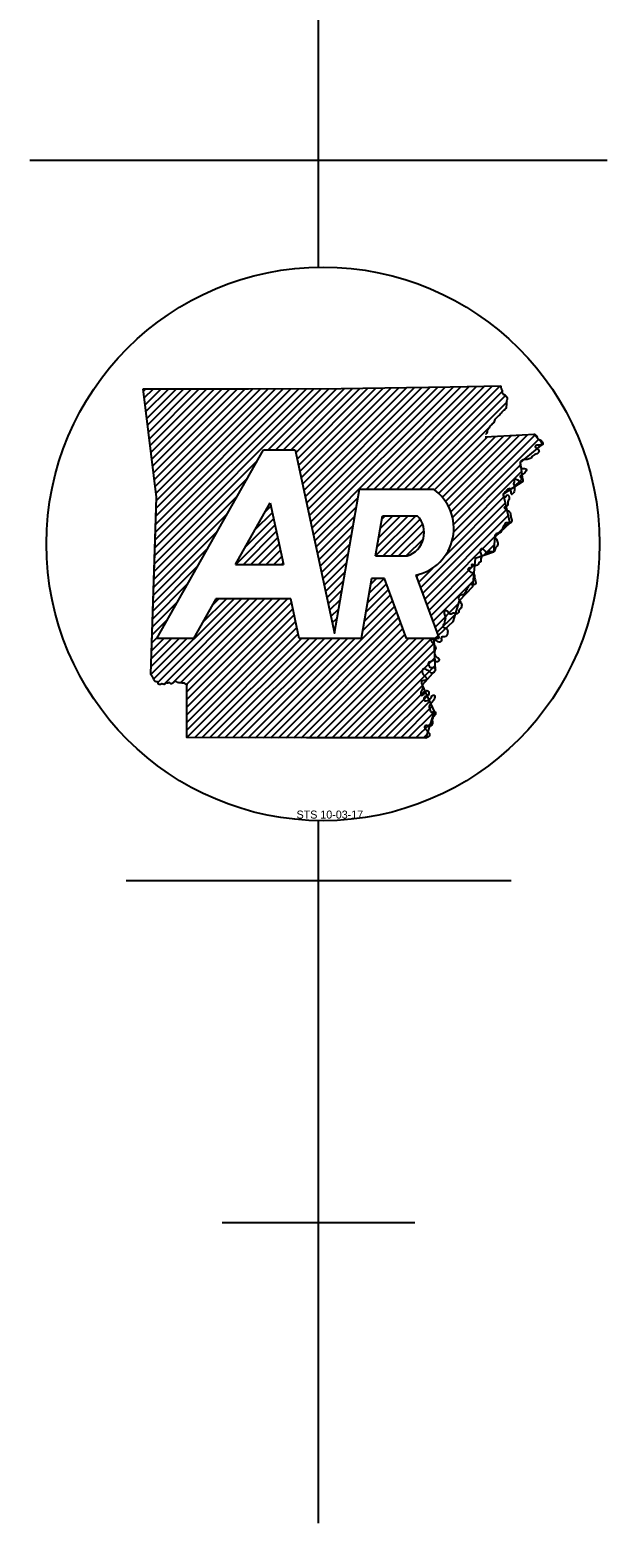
# Model space of a CAD drawing. Extents: x -24122 to 24238, y -8840 to 11381.
# Drawn here: x -5931 to -5405, y 2 to 1361 of the extents above; entities that cross this region are included whole.
import ezdxf

# ---------------------------------------------------------------- set-up
doc = ezdxf.new("R2010")
doc.units = 0
doc.layers.add('R_Annotation', color=7, linetype='Continuous')

msp = doc.modelspace()

# ---------------------------------------------------------------- linework, layer by layer
at = {"layer": 'R_Annotation'}
for p, q in [((-5667.7, 1145.2), (-5667.7, 2721.1)), ((-5930.9, 1242.6), (-5404.6, 1242.6)), ((-5827.3, 1032.3), (-5825.2, 1034.5)), ((-5826.6, 1026.1), (-5818.2, 1034.5)), ((-5825.8, 1019.9), (-5811.2, 1034.5)), ((-5825, 1013.7), (-5804.3, 1034.5)), ((-5824.2, 1007.5), (-5797.3, 1034.5)), ((-5823.5, 1001.3), (-5790.4, 1034.5)), ((-5822.7, 995.1), (-5783.4, 1034.5)), ((-5821.9, 989), (-5776.4, 1034.5)), ((-5821.2, 982.8), (-5769.5, 1034.4)), ((-5820.4, 976.6), (-5762.5, 1034.4)), ((-5819.6, 970.4), (-5755.5, 1034.4)), ((-5818.8, 964.2), (-5748.6, 1034.4)), ((-5818.1, 958), (-5741.6, 1034.4)), ((-5817.3, 951.8), (-5734.7, 1034.4)), ((-5817.1, 882.4), (-5664.9, 1034.6)), ((-5816.8, 889.6), (-5671.8, 1034.6)), ((-5816.6, 896.8), (-5678.8, 1034.5)), ((-5816.5, 945.6), (-5727.7, 1034.4)), ((-5816.4, 904), (-5685.8, 1034.5)), ((-5816.1, 911.2), (-5692.8, 1034.5)), ((-5815.9, 918.4), (-5699.8, 1034.5)), ((-5815.8, 939.4), (-5720.7, 1034.4)), ((-5815.6, 925.6), (-5706.8, 1034.5)), ((-5815.4, 932.8), (-5713.7, 1034.5)), ((-5713.6, 978.8), (-5657.9, 1034.6)), ((-5706.7, 978.8), (-5650.9, 1034.6)), ((-5699.7, 978.8), (-5643.9, 1034.7)), ((-5692.7, 978.8), (-5636.8, 1034.8)), ((-5688.4, 976.2), (-5629.7, 1034.9)), ((-5687.2, 970.5), (-5622.7, 1035)), ((-5685.9, 964.7), (-5615.6, 1035.1)), ((-5684.7, 959), (-5608.5, 1035.2)), ((-5683.5, 953.3), (-5601.4, 1035.3)), ((-5682.3, 947.5), (-5594.4, 1035.4)), ((-5681, 941.8), (-5587.3, 1035.5)), ((-5679.8, 936), (-5580.2, 1035.6)), ((-5678.6, 930.3), (-5573.1, 1035.8)), ((-5677.3, 924.6), (-5566, 1035.9)), ((-5676.1, 918.8), (-5559, 1036)), ((-5674.9, 913.1), (-5551.9, 1036.1)), ((-5673.7, 907.4), (-5544.8, 1036.2)), ((-5672.4, 901.6), (-5537.7, 1036.4)), ((-5624, 943), (-5530.5, 1036.5)), ((-5617.1, 943), (-5523.4, 1036.7)), ((-5610.1, 943), (-5516.3, 1036.9)), ((-5603.1, 943), (-5509.1, 1037)), ((-5596.2, 943), (-5502, 1037.2)), ((-5589.2, 943), (-5500.5, 1031.8)), ((-5582.2, 943), (-5497.1, 1028.2)), ((-5575.3, 943), (-5496.2, 1022.1)), ((-5568.3, 943), (-5512.1, 999.3)), ((-5547.1, 922.5), (-5476.8, 992.8)), ((-5562, 942.4), (-5513.5, 990.9)), ((-5558.2, 939.2), (-5506.1, 991.3)), ((-5554.8, 935.7), (-5498.8, 991.7)), ((-5551.8, 931.7), (-5491.4, 992.1)), ((-5549.2, 927.3), (-5484.1, 992.4)), ((-5545.5, 917.1), (-5470.1, 992.5)), ((-5544.5, 911.1), (-5466.9, 988.7)), ((-5470, 978.7), (-5463.6, 985)), ((-5817.3, 875.2), (-5723.3, 969.2)), ((-5815, 807.2), (-5717.8, 978.8)), ((-5717.8, 978.8), (-5689, 978.8)), ((-5817.6, 868), (-5732.4, 953.1)), ((-5545.9, 895.8), (-5482.7, 959)), ((-5544.5, 904.2), (-5483.5, 965.2)), ((-5490.5, 944.2), (-5481.9, 952.8)), ((-5630.3, 943), (-5562.9, 943)), ((-5817.8, 860.7), (-5741.5, 937)), ((-5743.5, 874.6), (-5711.7, 930.7)), ((-5716.7, 922), (-5711.1, 927.6)), ((-5671.2, 895.9), (-5631.7, 935.4)), ((-5670, 890.1), (-5633.1, 927)), ((-5574.7, 853.1), (-5497.5, 930.3)), ((-5552, 882.7), (-5498.8, 936)), ((-5818, 853.5), (-5750.6, 921)), ((-5734.9, 889.9), (-5708.6, 916.1)), ((-5725.8, 905.9), (-5709.8, 921.9)), ((-5668.7, 884.4), (-5634.6, 918.5)), ((-5615.7, 882.2), (-5579, 918.8)), ((-5614.2, 890.6), (-5586, 918.8)), ((-5612.8, 899), (-5592.9, 918.8)), ((-5611.3, 907.4), (-5599.9, 918.8)), ((-5609.8, 915.9), (-5606.9, 918.8)), ((-5609.3, 918.8), (-5577.6, 918.8)), ((-5608.7, 882.2), (-5575.1, 915.7)), ((-5601.7, 882.2), (-5572.8, 911.1)), ((-5572.8, 848), (-5496.2, 924.6)), ((-5570.9, 842.9), (-5494.9, 919)), ((-5569.1, 837.8), (-5493.6, 913.3)), ((-5818.3, 846.3), (-5759.7, 904.9)), ((-5743.2, 874.6), (-5707.4, 910.4)), ((-5736.2, 874.6), (-5706.2, 904.6)), ((-5729.3, 874.6), (-5704.9, 898.9)), ((-5667.5, 878.7), (-5636.1, 910.1)), ((-5666.3, 872.9), (-5637.6, 901.7)), ((-5594.8, 882.2), (-5571.5, 905.4)), ((-5587.8, 882.2), (-5572.1, 897.9)), ((-5818.5, 839.1), (-5768.8, 888.9)), ((-5722.3, 874.6), (-5703.7, 893.2)), ((-5715.3, 874.6), (-5702.5, 887.4)), ((-5665.1, 867.2), (-5639, 893.2)), ((-5663.8, 861.5), (-5640.5, 884.8)), ((-5517.4, 882.5), (-5507.6, 892.3)), ((-5818.7, 831.9), (-5777.9, 872.8)), ((-5743.5, 874.6), (-5699.7, 874.6)), ((-5708.4, 874.6), (-5701.2, 881.7)), ((-5701.4, 874.6), (-5700, 876)), ((-5662.6, 855.7), (-5642, 876.4)), ((-5615.7, 882.2), (-5586.8, 882.2)), ((-5576.6, 858.2), (-5563.3, 871.4)), ((-5567.2, 832.7), (-5525.4, 874.5)), ((-5819, 824.7), (-5787, 856.7)), ((-5661.4, 850), (-5643.4, 867.9)), ((-5660.2, 844.2), (-5644.9, 859.5)), ((-5623.1, 839.5), (-5605.7, 856.9)), ((-5621.7, 847.9), (-5607.8, 861.8)), ((-5620.2, 856.3), (-5614.7, 861.8)), ((-5607.6, 861.8), (-5619.3, 861.8)), ((-5587.4, 807.2), (-5607.6, 861.8)), ((-5579, 864.7), (-5557.8, 807.2)), ((-5578.4, 863.3), (-5576.3, 865.4)), ((-5565.3, 827.6), (-5526.2, 866.8)), ((-5563.4, 822.6), (-5527, 859)), ((-5818, 770), (-5744.7, 843.2)), ((-5813.8, 767.2), (-5737.8, 843.2)), ((-5808.8, 765.2), (-5730.8, 843.2)), ((-5800.5, 766.6), (-5723.8, 843.2)), ((-5793.5, 766.7), (-5716.9, 843.2)), ((-5788, 765.2), (-5709.9, 843.2)), ((-5787.8, 751.5), (-5696, 843.2)), ((-5787.8, 758.4), (-5702.9, 843.2)), ((-5761.3, 843.2), (-5781.7, 807.2)), ((-5773.8, 821.2), (-5751.7, 843.2)), ((-5764.7, 837.2), (-5758.7, 843.2)), ((-5693, 843.2), (-5761.3, 843.2)), ((-5658.9, 838.5), (-5646.4, 851.1)), ((-5626.1, 822.6), (-5602, 846.7)), ((-5624.6, 831), (-5603.9, 851.8)), ((-5819.2, 817.5), (-5796.1, 840.7)), ((-5787.7, 744.5), (-5692.3, 839.9)), ((-5787.7, 737.6), (-5691.1, 834.2)), ((-5718, 716.7), (-5598.2, 836.5)), ((-5711.1, 716.7), (-5596.3, 831.4)), ((-5657.7, 832.8), (-5647.8, 842.6)), ((-5656.5, 827), (-5649.3, 834.2)), ((-5627.6, 814.1), (-5600.1, 841.6)), ((-5561.5, 817.5), (-5540.2, 838.8)), ((-5819.5, 810.3), (-5805.2, 824.6)), ((-5787.7, 730.6), (-5689.9, 828.5)), ((-5787.7, 723.7), (-5688.6, 822.7)), ((-5787.6, 716.8), (-5687.4, 817)), ((-5704.1, 716.7), (-5594.5, 826.4)), ((-5697.2, 716.7), (-5592.6, 821.3)), ((-5690.2, 716.7), (-5590.7, 816.2)), ((-5655.2, 821.3), (-5650.8, 825.7)), ((-5654, 815.6), (-5652.3, 817.3)), ((-5559.7, 812.4), (-5543.2, 828.9)), ((-5820.5, 774.4), (-5787.7, 807.2)), ((-5820.4, 781.5), (-5794.7, 807.2)), ((-5820.2, 788.7), (-5801.6, 807.2)), ((-5819.9, 795.9), (-5808.6, 807.2)), ((-5819.7, 803.1), (-5814.3, 808.6)), ((-5781.7, 807.2), (-5815, 807.2)), ((-5780.6, 716.8), (-5686.2, 811.3)), ((-5773.7, 716.8), (-5683.2, 807.2)), ((-5766.7, 716.8), (-5676.3, 807.2)), ((-5759.7, 716.8), (-5669.3, 807.2)), ((-5752.8, 716.8), (-5662.3, 807.2)), ((-5745.8, 716.8), (-5655.4, 807.2)), ((-5738.9, 716.8), (-5648.4, 807.2)), ((-5731.9, 716.7), (-5641.4, 807.2)), ((-5725, 716.7), (-5634.5, 807.2)), ((-5628.8, 807.2), (-5685.3, 807.2)), ((-5683.3, 716.7), (-5588.8, 811.1)), ((-5676.3, 716.6), (-5585.7, 807.2)), ((-5669.3, 716.6), (-5578.7, 807.2)), ((-5662.4, 716.6), (-5571.8, 807.2)), ((-5655.4, 716.6), (-5564.8, 807.2)), ((-5648.5, 716.6), (-5562.5, 802.6)), ((-5557.8, 807.2), (-5587.4, 807.2)), ((-5641.5, 716.6), (-5562.2, 795.9)), ((-5634.6, 716.6), (-5561.9, 789.3)), ((-5627.6, 716.6), (-5561.5, 782.6)), ((-5620.7, 716.6), (-5573, 764.2)), ((-5613.7, 716.5), (-5570.8, 759.4)), ((-5606.8, 716.5), (-5568.7, 754.6)), ((-5599.8, 716.5), (-5566.5, 749.8)), ((-5592.8, 716.5), (-5564.4, 745)), ((-5585.9, 716.5), (-5562.6, 739.8)), ((-5578.9, 716.5), (-5565.7, 729.7)), ((-5572, 716.5), (-5568.9, 719.6)), ((-5667.7, 1.5), (-5667.7, 641.1)), ((-5843.1, 586.7), (-5492.2, 586.7)), ((-5755.4, 275.2), (-5580, 275.2))]:
    msp.add_line(p, q, dxfattribs=at)
for points in [[(-5827.6, 1034.4), (-5731.5, 1034.4), (-5647.1, 1034.6), (-5547.7, 1036.1), (-5501.6, 1037.2)], [(-5827.6, 1034.5), (-5731.5, 1034.4), (-5647.2, 1034.6), (-5547.7, 1036.1), (-5501.6, 1037.2)], [(-5820.7, 774.5), (-5815.3, 935.7), (-5827.6, 1034.5)], [(-5817, 885.1), (-5815.3, 935.7), (-5827.6, 1034.4)], [(-5471.4, 993.1), (-5463.1, 984.4), (-5483.8, 967.3), (-5481.6, 950.1), (-5499.3, 938.4), (-5493.2, 912), (-5507, 899.4), (-5508.2, 885.8), (-5524.8, 879.8), (-5527.4, 854.2), (-5539.4, 841.4), (-5545.2, 822.1), (-5562.6, 806.1), (-5561.3, 777.9), (-5573.2, 764.7), (-5562.4, 740.5), (-5569.9, 716.5)], [(-5515.8, 990.8), (-5470.7, 993.1)], [(-5515.8, 990.8), (-5470.7, 993.1)], [(-5689, 978.8), (-5653.2, 811.8), (-5630.3, 943)], [(-5711.7, 930.7), (-5699.7, 874.6)], [(-5615.7, 882.2), (-5609.3, 918.8)], [(-5820.6, 774.5), (-5817, 885.1)], [(-5619.3, 861.8), (-5628.8, 807.2)], [(-5685.3, 807.2), (-5693, 843.2)], [(-5569.9, 716.4), (-5787.7, 716.8), (-5787.8, 764.9)], [(-5569.9, 716.5), (-5787.7, 716.8), (-5787.8, 764.9)]]:
    msp.add_lwpolyline(points, dxfattribs=at)
msp.add_ellipse((-5663.6, 893.2), major_axis=(252.1, 0), ratio=0.999976, dxfattribs=at)
for centre, major_axis, start_param, end_param in [((-5588, 907.4), (-43.6, 0), 1.777838, 4.099264), ((-5593.7, 903.4), (-22.3, 0), 1.887169, 3.90762)]:
    msp.add_ellipse(centre, major_axis=major_axis, ratio=0.999987, start_param=start_param, end_param=end_param, dxfattribs=at)
for points in [[(-5501.6, 1037.2), (-5501.3, 1034.6), (-5500.5, 1033.3), (-5500.4, 1030.7), (-5499.3, 1029.6), (-5497.6, 1028.6), (-5496.1, 1026.9), (-5495.7, 1024.9), (-5496.2, 1022.8), (-5496.3, 1020.4), (-5496.5, 1018.4), (-5496.9, 1016.6), (-5498.3, 1015.1), (-5499.7, 1014.1), (-5500.9, 1012.8), (-5501.8, 1011.5), (-5503.3, 1010.1), (-5504.9, 1008.6), (-5506.2, 1007.3), (-5507.4, 1005.6), (-5508, 1003.8), (-5509.3, 1002.5), (-5510.4, 1001.3), (-5511.9, 999.6), (-5512.6, 998.1), (-5513.9, 996.2), (-5514.2, 994.5), (-5515.1, 993), (-5515.2, 992.8)], [(-5501.6, 1037.2), (-5501.3, 1034.6), (-5500.4, 1033.2), (-5500.3, 1030.7), (-5499.3, 1029.7), (-5497.6, 1028.6), (-5496, 1026.9), (-5495.7, 1024.9), (-5496.2, 1022.8), (-5496.3, 1020.5), (-5496.5, 1018.4), (-5496.9, 1016.6), (-5498.3, 1015.1), (-5499.7, 1014), (-5500.9, 1012.8), (-5501.8, 1011.5), (-5503.3, 1010.1), (-5504.9, 1008.6), (-5506.1, 1007.3), (-5507.4, 1005.6), (-5508, 1003.8), (-5509.4, 1002.5), (-5510.4, 1001.3), (-5511.8, 999.7), (-5512.6, 998.1), (-5513.9, 996.2), (-5514.2, 994.4), (-5515.1, 993), (-5515.2, 992.8)], [(-5471.4, 993.1), (-5470.7, 993.1), (-5468.7, 991), (-5467.8, 989.2), (-5466.5, 988.2), (-5465, 987.7), (-5463.9, 986.3), (-5463.1, 984.8), (-5463.5, 983.5), (-5465.2, 983.4), (-5467.1, 983.1), (-5468.8, 983.1), (-5470.3, 981.9), (-5468.9, 980.3), (-5467.2, 978.8), (-5466.7, 977.2), (-5467.7, 975.7), (-5469.6, 974.9), (-5471.4, 974.1), (-5473.1, 972.7), (-5473.9, 971.4), (-5475.7, 970.8), (-5477.6, 970.2), (-5479.3, 970.1), (-5481.2, 969.7), (-5483, 968.8), (-5483.8, 967.3), (-5483.6, 965.1), (-5483.6, 962.8), (-5481.7, 962), (-5480, 961.9), (-5478.2, 961.1), (-5478.5, 959.7), (-5479.7, 958), (-5481.2, 956.7), (-5482.7, 956.1), (-5484, 954.8), (-5483.6, 953.6), (-5482.3, 952.8), (-5481.4, 951.4), (-5481.6, 950.2), (-5483, 949.3), (-5484.5, 949.6), (-5485.7, 951.1), (-5486.9, 951.6), (-5488.1, 952.1), (-5489.4, 951.4), (-5489.4, 949.6), (-5489.9, 947.8), (-5489.4, 946.4), (-5489, 944.5), (-5489, 943.1), (-5489.4, 941), (-5490.5, 939), (-5491.6, 938.3), (-5492.2, 940.6), (-5492.4, 942.4), (-5493.1, 943.5), (-5494, 943.5), (-5495.3, 942.7), (-5496.6, 941.3), (-5498.3, 939.8), (-5499.4, 938.3), (-5498.8, 936.5), (-5497.5, 936), (-5496.5, 936.4), (-5496, 937.6), (-5495, 937.7), (-5494, 935.9)], [(-5494, 935.9), (-5493.8, 934.2), (-5494.8, 932.3), (-5495.2, 930.5), (-5495, 928.6), (-5496.9, 927.6), (-5498.5, 926.4), (-5497.6, 925), (-5495.8, 923.7), (-5494, 922.7), (-5492.9, 921.7), (-5492.6, 919.3), (-5492.3, 917.7), (-5491.7, 915.6), (-5491.5, 914.1), (-5492.5, 912.3), (-5493.8, 911.9), (-5495.1, 912.3), (-5496.6, 912.5), (-5497.9, 911.3), (-5498.8, 909.6), (-5499.7, 908), (-5500.4, 906.5), (-5501, 905), (-5502.3, 903.2), (-5503.9, 902.9), (-5505.8, 902.4), (-5506.9, 901.1), (-5506.7, 898.9), (-5505.6, 897.5), (-5504.8, 895.6), (-5504.3, 894), (-5504.5, 892), (-5505.4, 890.5), (-5506.4, 889.6), (-5506.9, 887.7), (-5507.7, 886.2), (-5508.4, 885.8), (-5509.8, 885.9), (-5511.4, 886.2), (-5512.7, 886.1), (-5513.9, 885.5), (-5515.2, 885.8), (-5516.5, 887.3), (-5517.6, 888.4), (-5518.8, 888.8), (-5520, 888.1), (-5520.2, 886.1), (-5519.6, 884.1), (-5519.1, 881.4), (-5519.6, 879.7), (-5519.8, 877)], [(-5519.8, 877), (-5521.9, 875.4), (-5522.8, 873.8), (-5528.1, 874.2), (-5528, 872.4), (-5529.9, 871.4), (-5531.5, 870.2), (-5530.6, 868.8), (-5528.8, 867.5), (-5527, 866.5), (-5525.9, 865.5), (-5525.6, 863), (-5525.3, 861.5), (-5524.7, 859.3), (-5524.4, 857.8), (-5525.5, 856.1), (-5526.8, 855.7), (-5528.1, 856.1), (-5529.6, 856.2), (-5530.8, 855.1), (-5531.7, 853.4), (-5532.6, 851.7), (-5533.3, 850.3), (-5534, 848.7), (-5535.2, 846.9), (-5536.8, 846.7), (-5538.8, 846.2), (-5539.9, 844.9), (-5539.7, 842.7), (-5538.6, 841.2), (-5537.8, 839.3), (-5537.2, 837.8), (-5537.5, 835.7), (-5538.3, 834.2), (-5539.4, 833.3), (-5539.9, 831.5), (-5540.7, 830), (-5541.4, 829.6), (-5542.8, 829.7), (-5544.3, 830), (-5545.6, 829.9), (-5546.9, 829.2), (-5548.2, 829.6), (-5549.5, 831), (-5550.5, 832.1), (-5551.7, 832.5), (-5553, 831.9), (-5553.2, 829.9), (-5552.6, 827.9), (-5552.1, 825.1), (-5552.6, 823.5), (-5552.8, 820.7)], [(-5552.8, 820.7), (-5552.9, 820.7), (-5554, 819.3), (-5553.4, 817.2), (-5551.1, 816.4), (-5550, 814.4), (-5550, 812.6), (-5550.7, 810.2), (-5551.8, 809), (-5553.9, 808.5), (-5555.5, 808.2), (-5555.7, 805.5), (-5556.4, 804.1), (-5557.7, 803.7), (-5559.5, 804.6), (-5560.5, 805.1), (-5561.8, 805.7), (-5563.5, 806.6), (-5564.8, 806.4), (-5564.4, 803.8), (-5564.3, 803.7), (-5562.8, 801.8), (-5561.4, 800.2), (-5560.8, 798.4)], [(-5552.8, 820.7), (-5552.9, 820.7), (-5554, 819.3), (-5553.4, 817.2), (-5551.1, 816.4), (-5550, 814.4), (-5550, 812.6), (-5550.7, 810.2), (-5551.8, 809), (-5553.9, 808.5), (-5555.5, 808.2), (-5555.7, 805.5), (-5556.4, 804.1), (-5557.7, 803.7), (-5559.5, 804.6), (-5560.5, 805.1), (-5561.8, 805.7), (-5563.5, 806.6), (-5564.8, 806.4), (-5564.4, 803.8), (-5564.3, 803.7), (-5562.8, 801.8), (-5561.4, 800.2), (-5560.8, 798.4)], [(-5560.8, 798.4), (-5561.3, 797), (-5562, 794.6), (-5561.8, 792.6), (-5560.9, 790.9), (-5559.5, 789.9), (-5557.9, 788.6), (-5558.1, 786.5), (-5559, 785.7), (-5561.1, 786.2), (-5562.7, 787), (-5564, 786.6), (-5565.8, 785.7), (-5567.2, 785.4), (-5567.2, 782.6), (-5565.4, 780.6), (-5563.8, 780.6), (-5561.9, 780.4), (-5561.2, 778.2), (-5562.3, 776.4), (-5564.1, 775.6), (-5566.3, 776.6), (-5567.9, 777.8), (-5569.5, 778.8), (-5571.6, 779.3), (-5572.7, 779.1), (-5573.2, 776.6), (-5572.3, 774.4), (-5570.8, 772.8), (-5569.3, 770.8), (-5569.5, 769.3), (-5570.6, 768.9), (-5572.5, 768.5), (-5573.7, 767.9), (-5573.9, 767.4), (-5573.4, 765.4), (-5572.8, 763.2), (-5572.8, 761.5), (-5573.5, 760), (-5574.5, 757.6), (-5574.4, 756.1), (-5573.7, 755.3), (-5572.8, 755.6), (-5571.6, 756.4), (-5570.8, 757.4), (-5570.1, 758.6), (-5568.9, 759.6), (-5567.4, 758.7), (-5567, 756.8), (-5567.9, 755.2), (-5569.2, 754.5), (-5570.7, 753.9), (-5571.8, 752.6), (-5571.5, 751), (-5570.6, 750.2), (-5568.4, 750.7), (-5567, 751.3), (-5566.1, 752.1), (-5565.1, 753.1), (-5564.6, 754.2), (-5563.8, 755.2), (-5562.4, 755.5), (-5561.8, 754.7), (-5562, 752.6), (-5562.8, 750.7), (-5564, 749.1), (-5565.2, 748), (-5566.8, 745.5), (-5566.5, 743.3), (-5565.8, 741.4), (-5565.1, 740), (-5563.6, 740.3), (-5562, 740.5), (-5561.1, 739.7), (-5561.2, 738), (-5562.4, 736.4), (-5563.5, 734.9), (-5564.1, 732.8), (-5563.8, 731.2), (-5563.8, 729.9), (-5564.3, 728.4), (-5565.1, 727.6), (-5567.4, 727.6), (-5569.7, 727.9), (-5570.9, 727.2), (-5570.7, 725.2), (-5569.3, 723.7), (-5568.4, 722.9), (-5567, 721.2), (-5566.4, 719.9), (-5566.6, 718.7), (-5567.5, 717.6), (-5569.9, 716.4)], [(-5560.8, 798.4), (-5561.3, 797), (-5562, 794.6), (-5561.8, 792.6), (-5560.9, 790.9), (-5559.5, 789.9), (-5557.9, 788.6), (-5558.1, 786.5), (-5559, 785.7), (-5561.1, 786.2), (-5562.7, 787), (-5564, 786.6), (-5565.8, 785.7), (-5567.2, 785.4), (-5567.2, 782.6), (-5565.4, 780.6), (-5563.8, 780.6), (-5561.9, 780.4), (-5561.2, 778.2), (-5562.3, 776.4), (-5564.1, 775.6), (-5566.3, 776.6), (-5567.9, 777.8), (-5569.5, 778.8), (-5571.6, 779.3), (-5572.7, 779.1), (-5573.2, 776.6), (-5572.3, 774.4), (-5570.8, 772.8), (-5569.3, 770.8), (-5569.5, 769.3), (-5570.6, 768.9), (-5572.5, 768.5), (-5573.7, 767.9), (-5573.9, 767.4), (-5573.4, 765.4), (-5572.8, 763.2), (-5572.8, 761.5), (-5573.5, 760), (-5574.5, 757.6), (-5574.4, 756.1), (-5573.7, 755.3), (-5572.8, 755.6), (-5571.6, 756.4), (-5570.8, 757.4), (-5570.1, 758.6), (-5568.9, 759.6), (-5567.4, 758.7), (-5567, 756.8), (-5567.9, 755.2), (-5569.2, 754.5), (-5570.7, 753.9), (-5571.8, 752.6), (-5571.5, 751), (-5570.6, 750.2), (-5568.4, 750.7), (-5567, 751.3), (-5566.1, 752.1), (-5565.1, 753.1), (-5564.6, 754.2), (-5563.8, 755.2), (-5562.4, 755.5), (-5561.8, 754.7), (-5562, 752.6), (-5562.8, 750.7), (-5564, 749.1), (-5565.2, 748), (-5566.8, 745.5), (-5566.5, 743.3), (-5565.8, 741.4), (-5565.1, 740), (-5563.6, 740.3), (-5562, 740.5), (-5561.1, 739.7), (-5561.2, 738), (-5562.4, 736.4), (-5563.5, 734.9), (-5564.1, 732.8), (-5563.8, 731.2), (-5563.8, 729.9), (-5564.3, 728.4), (-5565.1, 727.6), (-5567.4, 727.6), (-5569.7, 727.9), (-5570.9, 727.2), (-5570.7, 725.2), (-5569.3, 723.7), (-5568.4, 722.9), (-5567, 721.2), (-5566.4, 719.9), (-5566.6, 718.7), (-5567.5, 717.6), (-5569.9, 716.4)], [(-5787.8, 764.9), (-5787.5, 764.8), (-5788.7, 765.6), (-5790.2, 766.3), (-5791.9, 766.5), (-5794.1, 766.8), (-5796, 766.9), (-5797.9, 768.2), (-5799.9, 766.9), (-5802.2, 765.9), (-5803.5, 767), (-5805.2, 766.3), (-5806.4, 766.6), (-5808.5, 765.2), (-5810.4, 765.7), (-5811.9, 765.3), (-5813.6, 765.4), (-5814, 767.4), (-5815.7, 767.7), (-5817.2, 768.5), (-5818.2, 770.6), (-5818.9, 772.2), (-5820.7, 774.5)], [(-5787.8, 764.9), (-5787.5, 764.8), (-5788.7, 765.6), (-5790.2, 766.3), (-5792, 766.4), (-5794.2, 766.7), (-5796, 766.9), (-5797.9, 768.2), (-5799.9, 766.9), (-5802.2, 765.9), (-5803.5, 767), (-5805.2, 766.3), (-5806.4, 766.7), (-5808.5, 765.2), (-5810.5, 765.7), (-5811.8, 765.3), (-5813.6, 765.4), (-5814, 767.4), (-5815.7, 767.7), (-5817.2, 768.5), (-5818.2, 770.6), (-5818.9, 772.2), (-5820.6, 774.5)]]:
    msp.add_spline(points, degree=3, dxfattribs=at)

# ---------------------------------------------------------------- texts
msp.add_text('STS 10-03-17', height=7.288, dxfattribs=at).set_placement((-5687.7, 643.1))

doc.saveas('drawing.dxf')
